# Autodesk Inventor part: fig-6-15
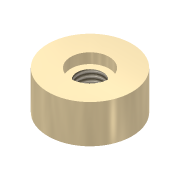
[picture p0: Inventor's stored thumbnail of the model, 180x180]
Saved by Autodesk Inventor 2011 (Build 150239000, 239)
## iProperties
Shininess: 65.0
Angle Display Precision: 2
Document Length Units: 11269
Document Angle Units: 11279
Document Time Units: 11290
Document Mass Units: 11283
Document Length Units Precision: 3
Document Angle Units Precision: 2
Created: 2001-11
Part Number: fig-6-15
Document SubType Name: Modeling
Designer: Renu Muthoo
Density: 1 g/cm^3
Density: 0.0
Volumn: 0.0
Area: 0.0
PropertySet Name: Model Information
Control State: 0
Master: False
Checked Out: False
Author: Renu Muthoo
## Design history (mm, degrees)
sketch "Sketch1"
  geometry: C1 r 16.401 at (0, 0)
  constraints: 1 centre point
extrude "Extrusion1" new body sketch "Sketch1" distance "d0" = 15; taper "d1" = 0 deg
hole "Hole3" diameter "d18" = 10.106; stored, may be unused: countersink angle "d22" = 90 deg, drill point angle "d24" = 118 deg; dims "d16" = 10, "d17" = 10, "d19" = 6, "d20" = 15, "d21" = 4, "d23" = 10
body "Solid1"
